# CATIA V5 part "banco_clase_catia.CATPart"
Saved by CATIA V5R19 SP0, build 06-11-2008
Part number: banco_clase_catia
Material "Pine": density 500 kg/m3, Young's modulus 1.7e+10 Pa, Poisson ratio 0.45, thermal expansion 3.75e-06 1/K
Bounding box of the stored display mesh (mm): x -1000 to 1000, y -475 to 475, z -910 to 40
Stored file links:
  C:\Users\Fran Robles\Desktop\Clase de Catia\banco_clase_catia.CATPart
  C:\Program Files\Dassault Systemes\B19\win_b64\startup\materials\Catalog.CATMaterial
  C:\Program Files\Dassault Systemes\B19\win_b64\startup\materials\pinetree.jpg
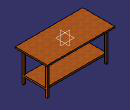
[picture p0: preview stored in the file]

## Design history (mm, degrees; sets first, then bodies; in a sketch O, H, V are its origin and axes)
Body1 (main body), material "Pine"
  Sketch1 on xy-plane, origin (0, 0, 0), H (1, 0, 0), V (0, 1, 0)
    line L1 (1000, 475) -> (1000, -475)
    line L2 (1000, -475) -> (-1000, -475)
    line L3 (-1000, -475) -> (-1000, 475)
    line L4 (-1000, 475) -> (1000, 475)
    length L2 = 2000
    length L1 = 950
    vertical: L1 V, L3 V
    horizontal: L2 H, L4 H
    equidistance: L1 L3 O, L2 L4 O
  Pad1: profile Sketch1, direction (0, 0, 1), length 40
  Sketch2 on start face of Pad1, origin (0, 0, 0), H (1, 0, 0), V (0, -1, 0)
    line L1 (900, 375) -> (900, -375)
    line L2 (900, -375) -> (-900, -375)
    line L3 (-900, -375) -> (-900, 375)
    line L4 (-900, 375) -> (900, 375)
    reference projected line E1 (-1000, 475) -> (1000, 475) from edge [start face of Pad1 | face of Pad1 from Sketch1.L2]
    reference projected line E2 (1000, 500) -> (1000, -500) from edge [start face of Pad1 | face of Pad1 from Sketch1.L1]
    line L5 (850, 325) -> (850, -325)
    line L6 (850, -325) -> (-850, -325)
    line L7 (-850, -325) -> (-850, 325)
    line L8 (-850, 325) -> (850, 325)
    distance L4 E1 = 100
    distance L1 E2 = 100
    distance L8 L4 = 50
    distance L5 L1 = 50
    vertical: L1 V, L3 V, L5 V, L7 V
    horizontal: L2 H, L4 H, L6 H, L8 H
    equidistance: L1 L3 O, L2 L4 O, L5 L7 O, L6 L8 O
  Pad2: profile Sketch2, direction (0, 0, -1), length 50
  Sketch3 on face of Pad2 from Sketch2.L1, origin (900, 0, 0), H (0, 1, 0), V (0, 0, 1)
    reference projected line E1 (375, -50) -> (-375, -50) from edge [face of Pad2 from Sketch2.L1 | end face of Pad2]
    point P1 (375, -50)
    line L1 (375, -50) -> (375, -910)
    point P3 (375, -910)
    line L2 (375, -910) -> (325, -910)
    point P4 (325, -910)
    line L3 (325, -910) -> (325, -710)
    point P5 (325, -710)
    line L4 (325, -710) -> (0, -710)
    point P6 (0, -710)
    construction line L5 (0, -710) -> (0, -660)
    point P7 (0, -660)
    line L6 (0, -660) -> (325, -660)
    point P8 (325, -660)
    line L7 (325, -660) -> (325, -50)
    point P9 (325, -50)
    line L8 (325, -50) -> (375, -50)
    reference projected line E2 (-500, 40) -> (500, 40) from edge [face of Pad1 from Sketch1.L1 | end face of Pad1]
    point P10 (-375, -910)
    point P11 (-375, -50)
    line L9 (-375, -50) -> (-375, -910)
    point P12 (-325, -50)
    line L10 (-325, -50) -> (-375, -50)
    point P13 (-325, -660)
    line L11 (-325, -660) -> (-325, -50)
    point P14 (0, -660)
    line L12 (0, -660) -> (-325, -660)
    point P15 (0, -710)
    point P16 (-325, -710)
    line L13 (-325, -710) -> (0, -710)
    point P17 (-325, -910)
    line L14 (-325, -910) -> (-325, -710)
    line L15 (-375, -910) -> (-325, -910)
    length L2 = 50
    length L5 = 50
    distance L4 L2 = 200
    distance L2 E2 = 950
    vertical: L1 V, L3 V, L5 V, L7 V
    horizontal: L2 H, L4 H, L6 H, L8 H
    coincidence: P8 L3, P9 E1, P7 V, P6 P15, P7 P14
    symmetry: P3 P10 V, P1 P11 V, L1 L9 V, P9 P12 V, L8 L10 V, P8 P13 V, L7 L11 V, P7 P14 V, L6 L12 V, P6 P15 V, P5 P16 V, L4 L13 V, P4 P17 V, L3 L14 V, L2 L15 V
  Pad3: profile Sketch3, direction (-1, 0, 0), length 50
  Mirror1: of the body so far, about yz-plane
  Sketch4 on face of Mirror1, origin (-850, 0, 0), H (0, 1, 0), V (0, 0, 1)
    line L1 (325, -660) -> (325, -710)
    line L2 (325, -710) -> (-325, -710)
    line L3 (-325, -710) -> (-325, -660)
    line L4 (-325, -660) -> (325, -660)
    vertical: L1 V, L3 V
    horizontal: L2 H, L4 H
  Pad4: profile Sketch4, direction (1, 0, 0), up to the existing solid (limit type 2)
